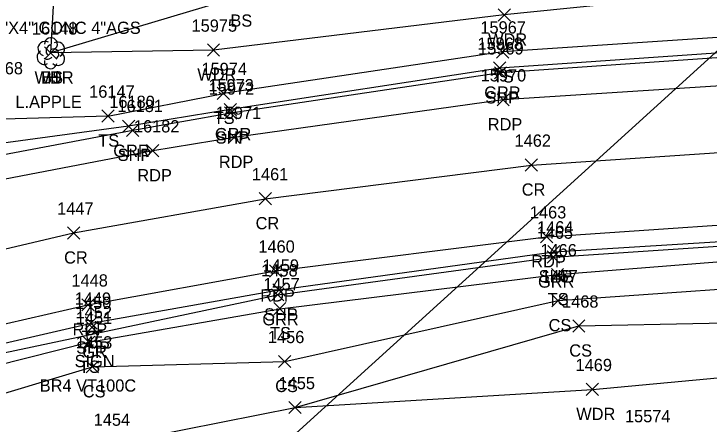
# Model space of a CAD drawing. Extents: x 1606530 to 1613020, y 784959 to 789666.
# Drawn here: x 1609153.1 to 1609266.7, y 788400.5 to 788467.6 of the extents above; entities that cross this region are included whole.
import ezdxf

# ---------------------------------------------------------------- set-up
doc = ezdxf.new("R2010")
doc.units = 0
for name, color, linetype in [('DCP', 7, 'Continuous'), ('L_A', 7, 'Continuous'), ('L_C', 7, 'Continuous'), ('L_I', 7, 'Continuous'), ('L_TIC', 7, 'Continuous'), ('LAWA', 7, 'Continuous'), ('LELB', 7, 'Continuous'), ('LTD', 7, 'Continuous'), ('M_C', 7, 'Continuous'), ('P_A', 7, 'Continuous'), ('P_I', 7, 'Continuous'), ('P_TIC', 7, 'Continuous'), ('PET', 7, 'Continuous'), ('PRC', 7, 'Continuous'), ('PSP', 7, 'Continuous'), ('R_A', 7, 'Continuous'), ('R_I', 7, 'Continuous'), ('R_TIC', 7, 'Continuous'), ('RGR', 7, 'Continuous'), ('S_A', 7, 'Continuous'), ('S_C', 7, 'Continuous'), ('S_I', 7, 'Continuous'), ('SSGN', 7, 'Continuous')]:
    doc.layers.add(name, color=color, linetype=linetype)

msp = doc.modelspace()

# ---------------------------------------------------------------- linework, layer by layer
at = {"layer": 'DCP'}
msp.add_lwpolyline([(1609180.84, 788382.35), (1609291.93, 788483.27)], dxfattribs=at)
at = {"layer": 'L_TIC'}
for points in [[(1609232.21, 788466.38), (1609234.21, 788468.38)], [(1609234.21, 788466.38), (1609232.21, 788468.38)], [(1609184.7, 788460.65), (1609186.7, 788462.65)], [(1609186.7, 788460.65), (1609184.7, 788462.65)], [(1609231.95, 788460.35), (1609233.95, 788462.35)], [(1609233.95, 788460.35), (1609231.95, 788462.35)], [(1609158.09, 788460.18), (1609160.09, 788462.18)], [(1609160.09, 788460.18), (1609158.09, 788462.18)], [(1609158.09, 788460.18), (1609160.09, 788462.18)], [(1609160.09, 788460.18), (1609158.09, 788462.18)], [(1609186.32, 788453.57), (1609188.32, 788455.57)], [(1609188.32, 788453.57), (1609186.32, 788455.57)], [(1609167.45, 788449.86), (1609169.45, 788451.86)], [(1609169.45, 788449.86), (1609167.45, 788451.86)], [(1609240.91, 788423.94), (1609242.91, 788425.94)], [(1609242.91, 788423.94), (1609240.91, 788425.94)], [(1609241.01, 788419.69), (1609243.01, 788421.69)], [(1609243.01, 788419.69), (1609241.01, 788421.69)], [(1609195.53, 788418.38), (1609197.53, 788420.38)], [(1609197.53, 788418.38), (1609195.53, 788420.38)], [(1609244.4, 788415.55), (1609246.4, 788417.55)], [(1609246.4, 788415.55), (1609244.4, 788417.55)], [(1609164.33, 788412.89), (1609166.33, 788414.89)], [(1609166.33, 788412.89), (1609164.33, 788414.89)], [(1609196.34, 788409.75), (1609198.34, 788411.75)], [(1609198.34, 788409.75), (1609196.34, 788411.75)], [(1609164.9, 788408.88), (1609166.9, 788410.88)], [(1609166.9, 788408.88), (1609164.9, 788410.88)], [(1609246.62, 788405.18), (1609248.62, 788407.18)], [(1609248.62, 788405.18), (1609246.62, 788407.18)], [(1609198.02, 788402.22), (1609200.02, 788404.22)], [(1609200.02, 788402.22), (1609198.02, 788404.22)], [(1609198.02, 788402.22), (1609200.02, 788404.22)], [(1609200.02, 788402.22), (1609198.02, 788404.22)]]:
    msp.add_lwpolyline(points, dxfattribs=at)
at = {"layer": 'LAWA'}
for points in [[(1609458.89, 788516.22), (1609465.52, 788489.74), (1609475.82, 788469.82), (1609458.93, 788473.78), (1609440.54, 788476.41), (1609422.32, 788472.18), (1609400.86, 788472.53), (1609378.74, 788469.08), (1609331.76, 788471.95), (1609305.7, 788472.62), (1609293.07, 788472.82), (1609275.81, 788471.77), (1609233.21, 788467.38), (1609185.7, 788461.65), (1609159.09, 788461.18), (1609160.3, 788482.23), (1609154.12, 788496.01), (1609177.08, 788505.79)], [(1609030.56, 788292.64), (1609056.03, 788324.44), (1609082.56, 788354.61), (1609090.16, 788369.42), (1609097.26, 788381.32), (1609109.23, 788386.03), (1609115.48, 788389.16), (1609124.65, 788392.27), (1609168.82, 788397.24), (1609199.02, 788403.22), (1609247.62, 788406.18), (1609289.08, 788410.02), (1609331.31, 788409.89), (1609380.07, 788411.97), (1609422.47, 788410.64), (1609441.9, 788412.64), (1609456.94, 788393.19), (1609459.97, 788389.84), (1609451.94, 788379.3), (1609445.61, 788371.6)]]:
    msp.add_lwpolyline(points, dxfattribs=at)
at = {"layer": 'LELB'}
for points in [[(1609288.12, 788482.43), (1609278.7, 788483.44), (1609240.78, 788478.4), (1609207.15, 788476.74), (1609190.02, 788470.47), (1609159.09, 788461.18)], [(1609570.41, 788453.62), (1609564.76, 788453.01), (1609526.4, 788455.39), (1609486.04, 788457.71), (1609468.83, 788462.11), (1609453.21, 788464.39), (1609423.17, 788463.36), (1609331.82, 788464.93), (1609285.23, 788464.87), (1609232.95, 788461.35), (1609187.32, 788454.57)], [(1609168.45, 788450.86), (1609187.32, 788454.57)], [(1609168.45, 788450.86), (1609147.57, 788450.22), (1609138.4, 788449.08), (1609125, 788446.82), (1609116.38, 788443.41), (1609109.47, 788440.87)], [(1608830.7, 788263.06), (1608870.16, 788285.39), (1608903.61, 788303.66), (1608913.17, 788310.86), (1608944.69, 788327.51), (1608982.09, 788348.33), (1609025.65, 788367.84), (1609062.43, 788383.44), (1609080.36, 788388.45), (1609093.56, 788391.85), (1609111.49, 788398.34), (1609124.29, 788403.55), (1609165.33, 788413.89), (1609196.53, 788419.38), (1609241.91, 788424.94), (1609287.83, 788428.62), (1609331.16, 788428.8), (1609379, 788428.23), (1609424.69, 788425.72), (1609443.9, 788424.45), (1609475.84, 788418.57), (1609486.48, 788419.99), (1609502.63, 788421.7)], [(1609108.11, 788392.39), (1609124.69, 788397.48), (1609165.9, 788409.88), (1609197.34, 788410.75), (1609242.01, 788420.69), (1609288.52, 788423.98), (1609330.87, 788426.64), (1609378.66, 788424.92), (1609423.8, 788422.52), (1609442.79, 788421.03), (1609475.94, 788416.79), (1609485.22, 788416.48)], [(1609199.02, 788403.22), (1609245.4, 788416.55), (1609288, 788417.43), (1609333.16, 788421.05), (1609378.48, 788420.63), (1609422.35, 788417.84)]]:
    msp.add_lwpolyline(points, dxfattribs=at)
at = {"layer": 'LTD'}
msp.add_line((1609159.09, 788461.18), (1609159.09, 788461.18), dxfattribs=at)
msp.add_line((1609159.09, 788461.18), (1609159.09, 788461.18), dxfattribs=at)
msp.add_arc((1609159.14, 788462.61), 1.05, 335.5272, 180.9563, dxfattribs=at)
for centre, major_axis, ratio, start_param, end_param in [((1609158.3, 788461.85), (1.21, -0.51), 0.895232, 1.570796, 4.712389), ((1609158.88, 788461.64), (-0.208, -0.792), 0.645439, 3.141593, 6.283185), ((1609160.13, 788461.76), (-1.14, -0.48), 0.949671, 1.570796, 4.712389), ((1609158.01, 788460.47), (0.58, -1.04), 0.959034, 3.141593, 6.283185), ((1609159.59, 788461.01), (-0.5, 0.667), 0.989748, 3.141593, 6.283185), ((1609160.09, 788460.35), (-1.09, 0.79), 0.841452, 1.570796, 4.712389), ((1609158.63, 788460.43), (-0.625, -0.083), 0.423636, 0, 3.141593), ((1609159.09, 788459.68), (0.26, 1.06), 0.942809, 1.570796, 4.712389)]:
    msp.add_ellipse(centre, major_axis=major_axis, ratio=ratio, start_param=start_param, end_param=end_param, dxfattribs=at)
at = {"layer": 'P_TIC'}
for points in [[(1609231.6, 788456.92), (1609233.6, 788458.92)], [(1609233.6, 788456.92), (1609231.6, 788458.92)], [(1609232.03, 788452.52), (1609234.03, 788454.52)], [(1609234.03, 788452.52), (1609232.03, 788454.52)], [(1609187.51, 788450.36), (1609189.51, 788452.36)], [(1609189.51, 788450.36), (1609187.51, 788452.36)], [(1609171.5, 788447.52), (1609173.5, 788449.52)], [(1609173.5, 788447.52), (1609171.5, 788449.52)], [(1609188.08, 788446.38), (1609190.08, 788448.38)], [(1609190.08, 788446.38), (1609188.08, 788448.38)], [(1609174.76, 788444.19), (1609176.76, 788446.19)], [(1609176.76, 788444.19), (1609174.76, 788446.19)], [(1609236.64, 788441.85), (1609238.64, 788443.85)], [(1609238.64, 788441.85), (1609236.64, 788443.85)], [(1609193.15, 788436.36), (1609195.15, 788438.36)], [(1609195.15, 788436.36), (1609193.15, 788438.36)], [(1609161.84, 788430.75), (1609163.84, 788432.75)], [(1609163.84, 788430.75), (1609161.84, 788432.75)], [(1609239.14, 788430.13), (1609241.14, 788432.13)], [(1609241.14, 788430.13), (1609239.14, 788432.13)], [(1609240.31, 788427.68), (1609242.31, 788429.68)], [(1609242.31, 788427.68), (1609240.31, 788429.68)], [(1609194.85, 788424.54), (1609196.85, 788426.54)], [(1609196.85, 788424.54), (1609194.85, 788426.54)], [(1609195.42, 788421.44), (1609197.42, 788423.44)], [(1609197.42, 788421.44), (1609195.42, 788423.44)], [(1609164.17, 788419), (1609166.17, 788421)], [(1609166.17, 788419), (1609164.17, 788421)], [(1609164.71, 788416.03), (1609166.71, 788418.03)], [(1609166.71, 788416.03), (1609164.71, 788418.03)]]:
    msp.add_lwpolyline(points, dxfattribs=at)
at = {"layer": 'PET'}
for points in [[(1609713.17, 788438.63), (1609680.93, 788440.45), (1609652, 788442.02), (1609625.85, 788443.73), (1609580.96, 788446.42), (1609565.08, 788447.47), (1609525.71, 788449.46), (1609486.16, 788451.54), (1609451.91, 788453.58), (1609423.87, 788454.94), (1609378.56, 788456.92), (1609332.01, 788457.67), (1609286.4, 788456.92), (1609233.03, 788453.52), (1609189.08, 788447.38), (1609175.76, 788445.19), (1609148.78, 788440), (1609127.71, 788434.8)], [(1608827.2, 788266.24), (1608867.86, 788290.54), (1608906.68, 788312.86), (1608942.68, 788332.75), (1608980.54, 788352.16), (1609023.57, 788373.22), (1609061.44, 788389.9), (1609090.8, 788401.17), (1609121.92, 788410.09), (1609165.17, 788420), (1609195.85, 788425.54), (1609240.14, 788431.13), (1609287.88, 788434.37), (1609331.48, 788435.11), (1609378.89, 788434.05), (1609425.43, 788432.25), (1609443.83, 788431.33), (1609477.32, 788429.78), (1609518.44, 788427.6), (1609569.18, 788424.68), (1609602.99, 788422.58), (1609641.45, 788420.37), (1609681.7, 788417.92), (1609727.38, 788415.53)]]:
    msp.add_lwpolyline(points, dxfattribs=at)
at = {"layer": 'PRC'}
msp.add_lwpolyline([(1608863.25, 788300.9), (1608901.81, 788322.6), (1608937.61, 788342.72), (1608976.12, 788362.76), (1609017.58, 788382.95), (1609062.58, 788402.24), (1609089.79, 788412.89), (1609118.81, 788421.44), (1609162.84, 788431.75), (1609194.15, 788437.36), (1609237.64, 788442.85), (1609286.9, 788446.16), (1609332.71, 788446.44), (1609379.39, 788445.34), (1609425.62, 788443.43), (1609445.83, 788442.47), (1609477.78, 788440.95), (1609519.76, 788438.85), (1609569.72, 788435.9), (1609601.73, 788434.31), (1609642.39, 788431.82), (1609682.03, 788429.15), (1609726.55, 788426.79)], dxfattribs=at)
at = {"layer": 'PSP'}
for points in [[(1609713.92, 788443.12), (1609681.22, 788444.65), (1609658, 788445.99), (1609646.32, 788446.92), (1609626.34, 788447.99), (1609592.68, 788450.1), (1609566.9, 788451.27), (1609526.22, 788453.59), (1609486.02, 788455.2), (1609451.52, 788457.02), (1609423.82, 788458.46), (1609378.09, 788460.47), (1609331.88, 788461.68), (1609285.23, 788461.6), (1609232.6, 788457.92), (1609188.51, 788451.36), (1609172.5, 788448.52), (1609147.32, 788443.74), (1609126.97, 788439.13), (1609114.12, 788436.45)], [(1608830.36, 788265), (1608869.22, 788287.4), (1608908.59, 788309.54), (1608943.86, 788329.41), (1608981.49, 788349.27), (1609025.12, 788370.21), (1609061.92, 788386.23), (1609076.39, 788391.44), (1609089.96, 788397.16), (1609122.92, 788407.13), (1609165.71, 788417.03), (1609196.42, 788422.44), (1609241.31, 788428.68), (1609287.88, 788431.58), (1609331.2, 788431.67), (1609378.92, 788430.28), (1609425.01, 788428.31)]]:
    msp.add_lwpolyline(points, dxfattribs=at)
at = {"layer": 'R_TIC'}
for points in [[(1609231.47, 788457.7), (1609233.47, 788459.7)], [(1609233.47, 788457.7), (1609231.47, 788459.7)], [(1609187.44, 788450.91), (1609189.44, 788452.91)], [(1609189.44, 788450.91), (1609187.44, 788452.91)], [(1609170.83, 788448.19), (1609172.83, 788450.19)], [(1609172.83, 788448.19), (1609170.83, 788450.19)], [(1609240.24, 788426.81), (1609242.24, 788428.81)], [(1609242.24, 788426.81), (1609240.24, 788428.81)], [(1609195.19, 788420.65), (1609197.19, 788422.65)], [(1609197.19, 788420.65), (1609195.19, 788422.65)], [(1609164.83, 788415.34), (1609166.83, 788417.34)], [(1609166.83, 788415.34), (1609164.83, 788417.34)]]:
    msp.add_lwpolyline(points, dxfattribs=at)
at = {"layer": 'RGR'}
for points in [[(1609451.62, 788460.78), (1609423.64, 788459.82), (1609378.06, 788461.13), (1609332.06, 788462.45), (1609285.08, 788462.33), (1609232.47, 788458.7), (1609188.44, 788451.91), (1609171.83, 788449.19), (1609146.47, 788445.79), (1609126.98, 788443.62)], [(1609093.56, 788395.55), (1609123.33, 788406.23), (1609196.19, 788421.65), (1609241.24, 788427.81), (1609287.73, 788430.93), (1609331.28, 788431.08), (1609378.86, 788429.59), (1609425.05, 788427.72), (1609442.61, 788426.23), (1609477.2, 788421.48)]]:
    msp.add_lwpolyline(points, dxfattribs=at)
at = {"layer": 'SSGN'}
for p, q in [((1609164.21, 788415.68), (1609167.55, 788415.68)), ((1609165.86, 788414.84), (1609165.86, 788414.84))]:
    msp.add_line(p, q, dxfattribs=at)
msp.add_circle((1609165.86, 788414.84), 0.833, dxfattribs=at)

# ---------------------------------------------------------------- texts
at = {"layer": 'L_A'}
for s, p in [('BS', (1609188.46, 788465.47)), ('WDR', (1609230.57, 788462.38)), ('WDR', (1609156.45, 788456.18)), ('BS', (1609157.53, 788456.18)), ('H', (1609158.52, 788456.18)), ('WDR', (1609183.06, 788456.65)), ('TS', (1609231.36, 788456.35)), ('TS', (1609185.73, 788449.57)), ('TS', (1609166.86, 788445.86)), ('TS', (1609240.32, 788419.94)), ('CS', (1609240.46, 788415.69)), ('TS', (1609194.94, 788414.38)), ('CS', (1609243.84, 788411.55)), ('TS', (1609163.74, 788408.89)), ('CS', (1609164.34, 788404.88)), ('CS', (1609195.78, 788405.75)), ('WDR', (1609244.98, 788401.18))]:
    msp.add_text(s, height=2, dxfattribs=at).set_placement(p)
at = {"layer": 'L_C'}
msp.add_text('L.APPLE', height=2, dxfattribs=at).set_placement((1609153.33, 788452.18))
at = {"layer": 'L_I'}
for s, p in [('16148', (1609156.02, 788464.18)), ('16148', (1609156.02, 788464.18)), ('16148', (1609156.02, 788464.18)), ('15975', (1609182.11, 788464.65)), ('15967', (1609229.31, 788464.35)), ('16168', (1609147.12, 788457.68)), ('16168', (1609147.12, 788457.68)), ('15974', (1609183.73, 788457.57)), ('16147', (1609165.38, 788453.86)), ('1466', (1609239.12, 788427.94)), ('1467', (1609239.27, 788423.69)), ('1457', (1609193.84, 788422.38)), ('1468', (1609242.66, 788419.55)), ('1451', (1609163.2, 788416.89)), ('1456', (1609194.59, 788413.75)), ('1453', (1609163.21, 788412.88)), ('1469', (1609244.87, 788409.18)), ('1455', (1609196.33, 788406.22)), ('1455', (1609196.33, 788406.22)), ('1454', (1609166.12, 788400.24)), ('15574', (1609252.94, 788400.81))]:
    msp.add_text(s, height=2, dxfattribs=at).set_placement(p)
at = {"layer": 'M_C'}
msp.add_text('4"X4" CONC 4"AGS', height=2, dxfattribs=at).set_placement((1609149.7, 788464.29))
at = {"layer": 'P_A'}
for s, p in [('SHP', (1609230.13, 788452.92)), ('RDP', (1609230.52, 788448.52)), ('SHP', (1609186.04, 788446.36)), ('SHP', (1609170.04, 788443.52)), ('RDP', (1609186.57, 788442.38)), ('RDP', (1609173.25, 788440.19)), ('CR', (1609236.07, 788437.85)), ('CR', (1609192.58, 788432.36)), ('CR', (1609161.28, 788426.75)), ('RDP', (1609237.63, 788426.13)), ('SHP', (1609238.84, 788423.68)), ('RDP', (1609193.34, 788420.54)), ('SHP', (1609193.96, 788417.44)), ('RDP', (1609162.66, 788415)), ('SHP', (1609163.25, 788412.03))]:
    msp.add_text(s, height=2, dxfattribs=at).set_placement(p)
at = {"layer": 'P_I'}
for s, p in [('15969', (1609228.95, 788460.92)), ('15970', (1609229.36, 788456.52)), ('15972', (1609184.92, 788454.36)), ('16181', (1609170, 788451.52)), ('15971', (1609186.05, 788450.38)), ('16182', (1609172.69, 788448.19)), ('1462', (1609234.9, 788445.85)), ('1461', (1609191.97, 788440.36)), ('1447', (1609160.15, 788434.75)), ('1463', (1609237.4, 788434.13)), ('1464', (1609238.57, 788431.68)), ('1460', (1609193.03, 788428.54)), ('1459', (1609193.72, 788425.44)), ('1448', (1609162.48, 788423)), ('1449', (1609163.01, 788420.03))]:
    msp.add_text(s, height=2, dxfattribs=at).set_placement(p)
at = {"layer": 'R_A'}
for s, p in [('GRR', (1609229.95, 788453.7)), ('GRR', (1609185.93, 788446.91)), ('GRR', (1609169.32, 788444.19)), ('GRR', (1609238.73, 788422.81)), ('GRR', (1609193.68, 788416.65)), ('GR', (1609164.26, 788411.34))]:
    msp.add_text(s, height=2, dxfattribs=at).set_placement(p)
at = {"layer": 'R_I'}
for s, p in [('15968', (1609228.83, 788461.7)), ('15973', (1609184.85, 788454.91)), ('16180', (1609168.67, 788452.19)), ('1465', (1609238.5, 788430.81)), ('1458', (1609193.5, 788424.65)), ('1450', (1609163.05, 788419.34))]:
    msp.add_text(s, height=2, dxfattribs=at).set_placement(p)
at = {"layer": 'S_A'}
msp.add_text('SIGN', height=2, dxfattribs=at).set_placement((1609163, 788409.82))
at = {"layer": 'S_C'}
msp.add_text('BR4 VT100C', height=2, dxfattribs=at).set_placement((1609157.3, 788405.82))
at = {"layer": 'S_I'}
msp.add_text('1452', height=2, dxfattribs=at).set_placement((1609163.15, 788417.82))

doc.saveas('drawing.dxf')
